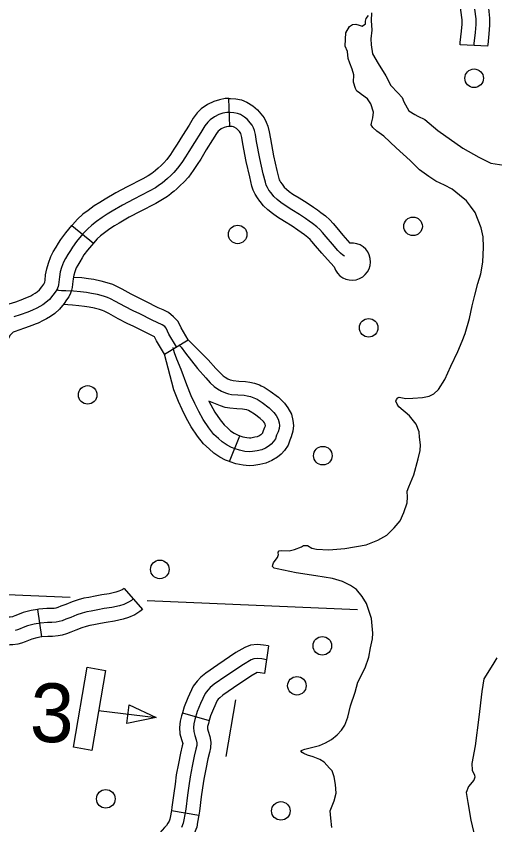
# Model space of a CAD drawing. Extents: x 653372 to 905732, y 627442 to 787275.
# Drawn here: x 712000 to 714580, y 745431 to 749788 of the extents above; entities that cross this region are included whole.
import ezdxf

# ---------------------------------------------------------------- set-up
doc = ezdxf.new("R2010")
doc.units = 0
for name, color, linetype in [('31', 7, 'Continuous'), ('32', 7, 'Continuous'), ('5', 7, 'Continuous'), ('56', 7, 'Continuous'), ('9', 7, 'Continuous')]:
    doc.layers.add(name, color=color, linetype=linetype)

msp = doc.modelspace()

# ---------------------------------------------------------------- linework, layer by layer
at = {"layer": '31'}
for p, q in [((713152, 749194.5), (713146.5, 749344.4)), ((713313.8, 748791.6), (713313.8, 748791.6)), ((712301.2, 748660.7), (712416.8, 748565)), ((712799.8, 747967.1), (712928.1, 748044.7)), ((712799.8, 747967.1), (712799.8, 747967.1)), ((713149.3, 747388.2), (713205.5, 747527.3))]:
    msp.add_line(p, q, dxfattribs=at)
for points in [[(713146.5, 749344.4), (713127.3, 749343.7), (713095.9, 749337.5), (713065.8, 749327.7), (713031.6, 749311.8), (712997.4, 749288.5), (712975.6, 749266.6), (712955.2, 749239), (712932.2, 749201.5), (712896.8, 749145.9), (712868.3, 749098.2), (712851, 749072.1), (712831.8, 749042.7), (712812, 749016.2), (712796.3, 748998.4), (712781.2, 748984.3), (712765.9, 748969.2), (712751.8, 748957.3), (712749.5, 748955.3)], [(713146.5, 749344.4), (713156.2, 749344.8), (713184.5, 749342.2), (713214.2, 749336.8), (713243.5, 749324.6), (713275.3, 749305.4), (713300.3, 749284.1), (713319.8, 749261.1), (713336.3, 749239.8), (713347.3, 749216.7), (713356.3, 749195.3), (713363.7, 749165), (713370.2, 749127), (713387.7, 749035.9), (713405, 748955.9), (713415.6, 748913.8), (713418.2, 748905.8), (713420.9, 748900), (713425.1, 748893.1), (713433.2, 748882.3)], [(713374.2, 748836), (713362.8, 748851.1), (713354.7, 748864.6), (713348.3, 748878.2), (713343.5, 748893.2), (713331.9, 748938.8), (713314.2, 749020.9), (713296.4, 749113.6), (713290.2, 749149.7), (713284.8, 749171.7), (713278.8, 749186), (713272, 749200.3), (713261.5, 749214), (713247.1, 749230.9), (713231.3, 749244.3), (713209.5, 749257.5), (713192.8, 749264.5), (713174.3, 749267.9), (713154.2, 749269.7), (713136, 749269), (713114.9, 749264.8), (713093.3, 749257.8), (713068.7, 749246.4), (713045.5, 749230.5), (713032.6, 749217.6), (713017.5, 749197.1), (712995.8, 749161.8), (712960.7, 749106.6), (712931.8, 749058.2), (712913.7, 749031), (712893.4, 748999.7), (712870.2, 748968.9), (712850.2, 748946.1), (712833.1, 748930.2), (712816.5, 748913.7), (712800.8, 748900.5), (712787.5, 748888.8), (712773.5, 748878.7), (712750.8, 748864), (712718, 748845.6), (712634.2, 748802.5), (712573.9, 748770), (712517.7, 748738), (712491, 748721.5), (712463.4, 748703.7), (712432.5, 748681.2), (712407.7, 748662.6), (712384.1, 748641.1), (712360.2, 748614.4), (712326.3, 748573.4), (712303.2, 748543.2), (712293, 748525.7), (712279, 748504.4), (712266.3, 748482.5), (712256, 748461.8), (712245, 748433.9), (712238.3, 748410.3), (712233.4, 748383.8), (712230.5, 748354.4), (712228, 748341), (712226.2, 748332.2), (712223.1, 748323), (712218.8, 748313.8), (712210.4, 748301.6), (712198.6, 748284.5), (712179.6, 748261.3), (712161.1, 748244.9), (712144.6, 748232.9), (712127.7, 748222.9), (712112.1, 748214.5), (712087.8, 748203.2), (712062.9, 748192.7), (712021.7, 748178.2), (711988.3, 748167.5)], [(713152, 749194.5), (713144.8, 749194.3), (713133.9, 749192.1), (713120.8, 749187.8), (713105.9, 749181), (713093.6, 749172.6), (713089.6, 749168.6), (713079.7, 749155.1), (713059.4, 749122), (713024.5, 749067.2), (712995.2, 749018.1), (712976.3, 748989.8), (712954.9, 748956.7), (712928.5, 748921.5), (712904, 748893.7), (712885.1, 748876.1), (712867.1, 748858.3), (712849.8, 748843.7), (712848.8, 748842.8)], [(713313.8, 748791.6), (713300.5, 748809.1), (713288.5, 748829.2), (713278.4, 748850.5), (713271.3, 748872.6), (713258.9, 748921.7), (713240.7, 749005.9), (713222.6, 749100.2), (713216.8, 749134.4), (713213.4, 749148), (713210.4, 749155.3), (713207.7, 749160.9), (713203.2, 749166.8), (713193.8, 749177.8), (713187.4, 749183.3), (713175.6, 749190.4), (713171.4, 749192.1), (713164.2, 749193.5), (713152.2, 749194.5), (713152, 749194.5)], [(712749.5, 748955.3), (712740.7, 748947.5), (712731.2, 748940.6), (712712.1, 748928.3), (712682.5, 748911.7), (712599.3, 748868.9), (712537.5, 748835.6), (712479.4, 748802.5), (712451, 748784.9), (712421.1, 748765.6), (712387.9, 748741.5), (712359.8, 748720.4), (712330.7, 748693.9), (712303.3, 748663.2), (712301.2, 748660.7)], [(713433.2, 748882.3), (713433.1, 748882.5), (713445.4, 748867.5), (713457.7, 748855.3), (713471.7, 748843.8), (713491.9, 748829.7), (713525, 748808.9), (713568.3, 748782.7), (713603.6, 748758.7), (713623.7, 748744.2), (713642.4, 748730.7), (713668.1, 748711.6), (713690.9, 748691.2), (713708.8, 748670.6), (713727.8, 748647.6), (713761.7, 748608.9), (713799, 748564.9)], [(712848.8, 748842.8), (712834.3, 748830), (712815.8, 748816.7), (712789.6, 748799.8), (712753.5, 748779.5), (712669.2, 748736.1), (712610.3, 748704.4), (712556, 748673.5), (712531, 748658), (712505.8, 748641.8), (712477.1, 748620.9), (712455.6, 748604.7), (712437.4, 748588.3), (712417.2, 748565.5), (712416.8, 748565)], [(713769.6, 748494.1), (713760.5, 748500.5), (713748.3, 748510.5), (713733.4, 748526.3), (713705, 748559.9), (713670.6, 748599), (713651.5, 748622.2), (713637.5, 748638.4), (713620.6, 748653.4), (713598.1, 748670.2), (713579.9, 748683.3), (713560.6, 748697.2), (713527.7, 748719.6), (713485.7, 748745.1), (713450.5, 748767.1), (713426.3, 748784), (713407.4, 748799.5), (713389.8, 748817), (713374.2, 748836)], [(713714.4, 748437.1), (713677.5, 748476.3), (713648.2, 748510.9), (713613.5, 748550.4), (713594.3, 748573.8), (713584, 748585.5), (713573.1, 748595.3), (713553.7, 748609.8), (713536.1, 748622.4), (713517.5, 748635.8), (713487.1, 748656.5), (713446.4, 748681.2), (713409, 748704.6), (713381, 748724.2), (713357.1, 748743.8), (713334.2, 748766.5), (713315.3, 748789.6), (713313.8, 748791.6)], [(712043.6, 748266), (712057.5, 748271.8), (712078.6, 748281.6), (712090.8, 748288.2), (712103.3, 748295.6), (712114, 748303.4), (712125.4, 748313.5), (712138.6, 748329.7), (712148.7, 748344.2), (712153.3, 748350.9), (712153.7, 748352.1), (712154.5, 748355.7), (712156.2, 748365), (712159.1, 748394.2), (712165.2, 748427.4), (712173.9, 748458), (712187.3, 748492.3), (712200.3, 748518.2), (712215.2, 748543.8), (712229.2, 748565.2), (712240.8, 748585.1), (712267.6, 748620.1), (712301.2, 748660.7)], [(712416.8, 748565), (712385, 748526.7), (712365.6, 748501.3), (712356.8, 748486.3), (712342.9, 748464.9), (712332.3, 748446.8), (712324.6, 748431.4), (712316.2, 748409.9), (712311.4, 748393.2), (712307.8, 748373.4), (712304.9, 748343.8), (712301.6, 748326.3), (712298.6, 748312.3), (712292.9, 748295.3), (712284.3, 748276.6), (712272.1, 748258.9), (712258.5, 748239.4), (712233.9, 748209.2), (712208.1, 748186.4), (712185.9, 748170.2), (712164.7, 748157.6), (712145.7, 748147.4), (712118.2, 748134.6), (712102.1, 748127.8)], [(712459.4, 748360.1), (712456.3, 748360.9), (712419.3, 748368.4), (712390.1, 748372.8), (712353.8, 748377.4), (712307.8, 748380.8)], [(712928.1, 748044.7), (712889.3, 748108.9), (712874.3, 748142.7), (712847.8, 748168.1), (712821.6, 748191.3), (712791.9, 748204.9), (712766.1, 748217.4), (712700.1, 748251.5), (712664, 748268.2), (712620.7, 748289.6), (712571.2, 748317.6), (712543.2, 748331.7), (712521.4, 748342.8), (712490.8, 748351.9), (712459.4, 748360.1)], [(712864, 748005.9), (712822.7, 748074.1), (712808.3, 748106.4), (712801.7, 748116.4), (712787.5, 748124.4), (712759.9, 748137), (712732.5, 748150.4), (712667.1, 748184.1), (712631.7, 748200.5), (712585.5, 748223.3), (712535.9, 748251.4), (712509.3, 748264.7), (712493.4, 748272.9), (712470.6, 748279.6), (712439.4, 748287.8), (712406.3, 748294.5), (712379.7, 748298.5), (712346.4, 748302.7), (712308.9, 748305.5), (712268.6, 748307.9), (712244.8, 748308.6), (712230.8, 748310.3), (712218.8, 748313.8)], [(711746.5, 748016.6), (711760.4, 748028.5), (711782.4, 748051.2), (711788.8, 748061.7), (711811.4, 748100.3), (711831.5, 748133.3), (711848.3, 748158.8), (711865.2, 748178.8), (711881.3, 748194.5), (711897.4, 748207.6), (711916.8, 748219.5), (711939.4, 748228.3), (711962.5, 748237.9), (711997.8, 748249.3), (712035.8, 748262.7), (712043.6, 748266)], [(712422.4, 748214.7), (712393.2, 748220.6), (712369.4, 748224.2), (712338.9, 748228.1), (712303.9, 748230.6), (712253.9, 748233.7)], [(712799.8, 747967.1), (712756.1, 748039.3), (712746.6, 748060.6), (712727.9, 748069.2), (712698.9, 748083.3), (712634.1, 748116.7), (712599.3, 748132.9), (712550.4, 748157), (712500.6, 748185.2), (712475.4, 748197.8), (712465.4, 748203), (712450.4, 748207.4), (712421.3, 748215)], [(712102.1, 748127.8), (712090, 748122.7), (712045.6, 748107.1), (712014.2, 748097), (711995.6, 748089.3), (711984.1, 748084.8), (711981.4, 748082.6), (711975, 748076.3), (711968.6, 748068.7), (711958.3, 748053), (711940.2, 748023.4), (711917.7, 747985), (711902, 747959), (711863.2, 747919), (711842.3, 747901.2)], [(712928.1, 748044.7), (713034.9, 747936.7), (713077.2, 747889.5), (713099.9, 747865.7), (713116, 747850.2), (713126.1, 747842.6), (713140.4, 747834.5), (713154.4, 747828.7), (713162.7, 747825.9), (713170.2, 747824.7), (713200.4, 747822.1), (713236.4, 747820.1), (713259.2, 747816.4), (713284, 747810.9), (713311.6, 747801.2), (713321.2, 747796.3)], [(712877.2, 748018), (712889.1, 748004.9), (712913.5, 747972.1), (712977.1, 747888.8), (713022.1, 747838.5), (713046.7, 747812.8), (713067.3, 747793), (713084.8, 747779.8), (713107.4, 747766.9), (713128.1, 747758.4), (713144.6, 747752.9), (713160.9, 747750.2), (713195, 747747.2), (713228.3, 747745.4), (713245, 747742.7), (713263.4, 747738.6), (713281.9, 747732.1), (713298.9, 747723.5), (713326.7, 747705.7), (713364.5, 747677.7), (713389.4, 747653), (713401.9, 747636.8), (713412.9, 747616.2), (713417.3, 747597.7), (713418.8, 747581.8), (713417.3, 747566.8), (713411.9, 747547.8), (713404.1, 747530.1), (713398.2, 747510.7), (713387.4, 747495.6), (713375.5, 747482.6), (713364.1, 747472.8), (713343.8, 747460.2), (713323.6, 747451.4), (713300, 747446.7), (713273.2, 747442.1), (713256.7, 747441.1), (713233.6, 747443.2), (713203.4, 747448.8), (713180.6, 747456.5), (713160.9, 747464.5), (713136.7, 747477.3), (713110.9, 747494), (713090.3, 747511.8), (713066.4, 747534.7), (713038.9, 747569.3), (713007.9, 747615), (712984, 747658.4), (712963.2, 747701.2), (712944.3, 747741.9), (712920.4, 747802), (712889, 747884.5), (712866.5, 747940.3), (712853.6, 747974.6), (712849.4, 747986.6), (712846.4, 748002.6)], [(713149.3, 747388.2), (713129.2, 747396.4), (713098.7, 747412.5), (713065.6, 747434), (713039.8, 747456.3), (713010.8, 747484), (712978.4, 747524.9), (712943.9, 747575.8), (712917.4, 747623.9), (712895.4, 747669), (712875.4, 747712.3), (712850.5, 747774.8), (712799.8, 747967.1)], [(713321.2, 747796.3), (713336.2, 747788.6), (713369.3, 747767.5), (713413.5, 747734.7), (713445.7, 747702.8), (713465.2, 747677.7), (713483.6, 747643), (713491.5, 747610), (713494.2, 747581.6), (713491.3, 747552.8), (713482.7, 747522.2), (713474.5, 747503.8), (713466.4, 747477.2), (713445.9, 747448.4), (713427.8, 747428.6), (713408.5, 747412.1), (713378.7, 747393.7), (713346.2, 747379.3), (713313.6, 747373), (713281.8, 747367.4), (713255.5, 747366), (713223.4, 747368.8), (713184.5, 747376.1), (713154.6, 747386.1), (713149.3, 747388.3)], [(713253, 747662.7), (713252.3, 747663), (713242.8, 747666.4), (713230.9, 747669), (713220.2, 747670.8), (713189.7, 747672.4), (713151.7, 747675.8), (713126.5, 747679.8), (713101.9, 747688.1), (713039, 747713.9)], [(713039, 747713.9), (713071.9, 747654.2), (713099.4, 747613.7), (713121.9, 747585.4), (713140.8, 747567.4), (713156.1, 747554.1), (713174.7, 747542), (713192.6, 747532.6), (713205.5, 747527.3)], [(713205.5, 747527.3), (713206.6, 747526.9), (713222.4, 747521.6), (713243.9, 747517.6), (713257.9, 747516.3), (713264.6, 747516.7), (713286.3, 747520.5), (713301.1, 747523.4), (713308.8, 747526.8), (713319.7, 747533.5), (713323.2, 747536.5), (713329, 747542.8), (713330, 747544.3), (713333.7, 747556.3), (713341.2, 747573.3), (713343.4, 747580.8), (713343.5, 747582), (713343.1, 747585.4), (713342.2, 747589.5), (713338.7, 747596), (713333.1, 747603.2), (713315.6, 747620.6), (713284.1, 747643.9), (713261.6, 747658.3), (713253, 747662.7)]]:
    msp.add_lwpolyline(points, dxfattribs=at)
msp.add_arc((713810.3, 748465.5), 100, 196.5446, 96.4681, dxfattribs=at)
at = {"layer": '32'}
for p, q in [((714543.2, 749626.7), (714393.4, 749633.7)), ((712582.2, 746704.2), (712681.5, 746591.8)), ((712114.7, 746591.2), (712137.3, 746442.9)), ((713360.7, 746394.7), (713338.9, 746246.3)), ((712896.3, 746034.2), (713040.6, 745993)), ((712837, 745507.7), (712985, 745483.1))]:
    msp.add_line(p, q, dxfattribs=at)
for points in [[(714393.4, 749633.7), (714394, 749646.2), (714400.9, 749707.2), (714403.9, 749745.9), (714403.8, 749768.6), (714397.5, 749821), (714396.3, 749860.7), (714399, 749909.5), (714409, 749947.5), (714422.3, 749979.9), (714449.7, 750029.4), (714481.1, 750071.2), (714509.2, 750102.2), (714531.6, 750125.1), (714546.8, 750143.7), (714558.6, 750158)], [(714543.2, 749626.7), (714543.6, 749634.2), (714550.3, 749693), (714553.9, 749740.4), (714553.8, 749777.9), (714547.2, 749832.2), (714546.4, 749858.7), (714547.9, 749886), (714551.6, 749899.8), (714557.8, 749914.9), (714575.9, 749947.7), (714596.8, 749975.5), (714618.4, 749999.3), (714643.6, 750025.1), (714662.7, 750048.5), (714674.2, 750062.4)], [(714468.3, 749630.2), (714468.8, 749640.2), (714475.6, 749700.1), (714478.9, 749743.2), (714478.8, 749773.2), (714472.4, 749826.6)], [(712582.2, 746704.2), (712577.8, 746700.3), (712571.2, 746696.3), (712554.1, 746689), (712537.2, 746683.7), (712501.9, 746675.5), (712461.3, 746669.6), (712426.1, 746662.9), (712391.7, 746655.7), (712365.9, 746651.6), (712335.2, 746643.5), (712301.9, 746632.6), (712267.3, 746618.4), (712240.7, 746608.5), (712224.5, 746601.9), (712213.6, 746599), (712204.7, 746597.1), (712189.5, 746596), (712164.9, 746595.6), (712122.5, 746592.4), (712114.6, 746591.2)], [(712631.8, 746648), (712622.5, 746639.8), (712605.9, 746629.6), (712580.1, 746618.5), (712556.7, 746611.3), (712515.8, 746601.8), (712473.8, 746595.7), (712440.8, 746589.3), (712405.3, 746581.9), (712381.4, 746578.1), (712356.4, 746571.5), (712327.8, 746562.2), (712294.7, 746548.5), (712267.8, 746538.6), (712248.4, 746530.7), (712231.3, 746526.1), (712215.4, 746522.7), (712192.7, 746521.1), (712168.4, 746520.7), (712131, 746517.8), (712097, 746512.6), (712061.4, 746503), (712037.4, 746493.5), (712021.3, 746486.1), (712007.1, 746481.4), (711994.5, 746477.9)], [(712114.7, 746591.2), (712081.4, 746586.1), (712037.7, 746574.3), (712007.8, 746562.5), (711993.8, 746556), (711985.1, 746553.2), (711979.8, 746551.6), (711967.9, 746550.3), (711952.3, 746549), (711920.3, 746545), (711879, 746534.2), (711832.9, 746517.4), (711779.8, 746493.1), (711732.1, 746467.9), (711695, 746451), (711681.4, 746446.5), (711656.9, 746441.9), (711564.8, 746435.5)], [(712681.5, 746591.8), (712667.3, 746579.3), (712640.5, 746562.8), (712606.1, 746548), (712576.3, 746538.8), (712529.6, 746528), (712486.3, 746521.7), (712455.5, 746515.8), (712418.8, 746508.2), (712396.9, 746504.7), (712377.6, 746499.6), (712353.8, 746491.8), (712322, 746478.7), (712294.9, 746468.7), (712272.3, 746459.5), (712249, 746453.2), (712226, 746448.2), (712195.9, 746446.1), (712171.9, 746445.7), (712139.5, 746443.3), (712137.3, 746442.9)], [(712137.3, 746442.9), (712112.5, 746439.1), (712085, 746431.7), (712066.9, 746424.5), (712048.8, 746416.2), (712029, 746409.7), (712009.3, 746404.1), (711982.6, 746401), (711967.6, 746399.7), (711948.6, 746397.4), (711923.8, 746390.9), (711889.9, 746378.5), (711846, 746358.4), (711798.3, 746333.3), (711749.6, 746311), (711718.7, 746300.9), (711676.1, 746292.9), (711638.8, 746290.3), (711580.6, 746293.5)], [(713360.7, 746394.7), (713333.5, 746398.7), (713301.1, 746402), (713263.6, 746399.5), (713233, 746386.6), (713184.8, 746358.5), (713087.6, 746293.1), (713022.8, 746248.5), (712995.8, 746225.9), (712975.4, 746205.1), (712954.7, 746177.3), (712925.9, 746115.3), (712905.6, 746066.8), (712896.3, 746034.2)], [(713349.8, 746320.5), (713324.2, 746324.3), (713299.7, 746326.8), (713281.2, 746325.5), (713266.6, 746319.4), (713224.7, 746295), (713129.9, 746231.1), (713068.2, 746188.7), (713046.8, 746170.8), (713032.6, 746156.3), (713019.5, 746138.7), (712994.6, 746085.1), (712976.5, 746041.9), (712963.8, 745997.5), (712957.8, 745975.5), (712955.4, 745954.7), (712957.1, 745933.7), (712963.1, 745912.6), (712971.3, 745888.4), (712974.4, 745871.6), (712973.4, 745857.9), (712968.6, 745838.3), (712959.9, 745801.3), (712949.2, 745746), (712937.3, 745688.4), (712931.1, 745640.1), (712923.7, 745591.3), (712914.2, 745514.5), (712904.7, 745457.3), (712901.2, 745438.8), (712892.1, 745416.9)], [(713338.9, 746246.3), (713314.9, 746249.8), (713299, 746251.5), (713264.5, 746231.4), (713172.1, 746169.1), (713113.6, 746128.8), (713097.7, 746115.6), (713089.7, 746107.4), (713084.2, 746100.1), (713063.2, 746054.8), (713047.4, 746017.1), (713040.6, 745993)], [(712896.3, 746034.2), (712891.6, 746017.7), (712884, 745989.9), (712880, 745955.9), (712883, 745920.3), (712891.4, 745890.3), (712898.6, 745869.5), (712898.8, 745868.3), (712895.7, 745855.8), (712886.5, 745817), (712875.7, 745760.7), (712863.3, 745700.8), (712856.8, 745650.6), (712849.4, 745601.6), (712839.9, 745525.2), (712837, 745507.7)], [(713040.6, 745993), (713036.1, 745977.2), (713031.6, 745961.2), (713030.7, 745953.5), (713031.3, 745947.1), (713034.7, 745934.9), (713044.1, 745907.4), (713049.9, 745875.7), (713047.7, 745846.2), (713041.5, 745820.8), (713033.2, 745785.6), (713022.8, 745731.4), (713011.4, 745676), (713005.4, 745629.7), (712998, 745581.1), (712988.4, 745503.7), (712985, 745483.1)], [(712837, 745507.7), (712830.9, 745470.5), (712828.9, 745460.4), (712824.7, 745450.2), (712818.5, 745439.4), (712811.3, 745427.1), (712800.5, 745415.4), (712762.2, 745373.1), (712733.7, 745343.7), (712685.3, 745308.4), (712613.3, 745261.1)], [(712985, 745483.1), (712978.5, 745444.2), (712973.4, 745417.2), (712959.6, 745383.7), (712948.1, 745364), (712932.6, 745337.4), (712911.3, 745314.3), (712871.7, 745270.4), (712803.5, 745200.4)]]:
    msp.add_lwpolyline(points, dxfattribs=at)
at = {"layer": '5'}
for points in [[(712290.9, 746655.2), (711527, 746687.9)], [(713839.3, 746588.9), (712706.3, 746637.4)]]:
    msp.add_lwpolyline(points, dxfattribs=at)
at = {"layer": '56'}
for p, q in [((712596.9, 745976.8), (712609.5, 746078)), ((712609.5, 746078), (712755.1, 746008.5)), ((712755.1, 746008.5), (712596.9, 745976.8))]:
    msp.add_line(p, q, dxfattribs=at)
msp.add_lwpolyline([(712383.2, 746279.5), (712481.8, 746262.7), (712408.2, 745831.4), (712309.7, 745848.2)], close=True, dxfattribs=at)
for points in [[(713182.5, 746103.4), (713130.6, 745799)], [(712445, 746047), (712755.1, 746008.5)]]:
    msp.add_lwpolyline(points, dxfattribs=at)
for centre in [(714468.5, 749453.7), (714139.4, 748655.6), (713194, 748612.1), (713900.2, 748109), (712385.7, 747747.4), (713653.1, 747419.8), (712774.6, 746806.9), (713650.5, 746395.3), (713513.3, 746180), (712483.4, 745570.5), (713427, 745505.6)]:
    msp.add_circle(centre, 50, dxfattribs=at)
at = {"layer": '9'}
for points in [[(714557.8, 748995.4), (714629.3, 748985.8), (714700.8, 749002.5), (714762, 749021.6), (714811.4, 749066.1), (714901.7, 749149.1), (714975.3, 749234.7), (715045.3, 749337.2), (715083.1, 749413.4), (715099.3, 749465.2), (715106, 749479.6), (715132.1, 749512.3), (715171.4, 749569.7), (715204.4, 749623), (715257.7, 749728.1), (715315, 749826.7)], [(714507.3, 748647.3), (714473.2, 748729.6), (714449.5, 748764.5), (714426.8, 748793.5), (714388.9, 748824.1), (714349.8, 748855.9), (714309.2, 748878.4), (714262.7, 748898.6), (714224.6, 748924.5), (714173.8, 748960.2), (714124.6, 749010), (714048.9, 749078.3), (713982.5, 749141.6), (713944.4, 749168.7), (713922.6, 749188.2), (713913.6, 749202.6), (713916.2, 749212), (713923, 749241.2), (713926.3, 749271.8), (713912.3, 749315.8), (713893, 749342.3), (713862, 749366.8), (713845.8, 749378.6), (713836.6, 749384.8), (713828.8, 749399.2), (713819.2, 749432.5), (713820.4, 749472.5), (713811.9, 749503.4), (713798.7, 749534.4), (713790, 749560.6), (713785.2, 749597.3), (713774.3, 749625.9), (713775.4, 749663.6), (713777.7, 749698.9), (713797.5, 749732.5), (713813.2, 749742.6), (713830.9, 749745.6), (713848.4, 749739.2), (713866, 749735.2), (713882.8, 749746.4), (713883.3, 749761.8), (713886, 749775.8), (713899.5, 749791.9)], [(713915.2, 749806.8), (713912.8, 749765.6), (713917.2, 749713.6), (713911, 749666.6), (713913.6, 749633.5), (713921.5, 749585)], [(713921.5, 749585), (713950.6, 749533.4), (713992.2, 749466.2), (714018.9, 749414.7), (714056.6, 749374.6), (714080.6, 749350.3), (714090.5, 749326.5), (714117.4, 749278.5), (714148.6, 749258.7), (714166, 749249.9), (714203.1, 749231.2), (714272, 749171.3), (714408.3, 749077.7), (714494, 749027.9), (714557.8, 748995.4)], [(713549.8, 746935.9), (713569.8, 746936.5), (713594.1, 746921.6), (713618.7, 746916.2), (713685.8, 746913), (713770.8, 746919.9), (713886.9, 746938.8), (713948.9, 746964), (713998, 746992), (714036.9, 747030.9), (714069.9, 747068.8), (714090.1, 747113.6), (714106.9, 747165), (714109.1, 747196.8), (714107.7, 747228.6), (714116.6, 747251.9), (714143.3, 747317.1), (714167.1, 747402.5), (714177.9, 747448.1), (714179.9, 747477.5), (714174.1, 747519), (714171.5, 747548.5), (714156.2, 747589), (714119.8, 747633.7), (714063.6, 747683.8), (714054.6, 747697), (714046.8, 747713.7), (714050.6, 747721.9), (714058, 747732.3), (714065.1, 747734.4), (714100.3, 747728.6), (714138, 747729.8), (714190, 747733), (714226.7, 747740.2), (714250.6, 747752.4), (714277.3, 747776.4), (714310.7, 747829.6), (714343.5, 747901.7), (714381.3, 747981.9), (714404.1, 748036.6), (714419.5, 748078.5), (714443.1, 748158.8), (714458.1, 748226.7), (714472.8, 748284), (714488.9, 748348.4), (714504.6, 748399.7), (714515.9, 748463), (714518.3, 748543.2), (714517.6, 748598.7), (714507.3, 748647.3)], [(713715, 745688.7), (713704.2, 745720.9), (713688.2, 745736.7), (713659.6, 745768.2), (713636.5, 745781.8), (713601.6, 745797), (713570, 745805.1), (713550.3, 745815.1), (713541, 745820.1), (713534.2, 745828.5), (713536.7, 745832), (713556.9, 745838.4), (713635.2, 745857.3), (713667.5, 745871.7), (713699.9, 745890.7), (713731.2, 745915.7), (713753.2, 745941), (713771.7, 745968.1), (713787.1, 746010.1), (713803.1, 746072.1), (713826.5, 746145.7), (713841.1, 746199.4), (713881.1, 746276), (713901.7, 746334.4), (713910.3, 746384.8), (713921.2, 746432.8), (713923.3, 746463.4), (713915, 746541.9), (713889.2, 746624), (713865.5, 746660.1), (713834.9, 746698.7), (713802.5, 746720.9), (713758.4, 746741.1), (713705.9, 746758), (713615.6, 746772.5), (713510, 746788.6), (713407, 746810.6), (713391.7, 746813.4), (713382.6, 746821.9), (713384, 746831.3), (713387.9, 746843), (713396.5, 746854.5), (713408.8, 746871.8), (713414, 746888.1), (713411.9, 746895.3), (713412, 746900), (713418.1, 746906.9), (713428.8, 746908.9), (713472.3, 746907.6), (713499.6, 746913.9), (713537.8, 746929.2), (713549.8, 746935.9)], [(714591.1, 746329.9), (714569.1, 746295)], [(714569.1, 746295), (714520.8, 746217.2), (714510.4, 746148.6), (714493.7, 746011.1), (714474.5, 745856.9), (714457, 745761.3), (714458, 745725.7), (714469.7, 745698.1), (714471.5, 745687.6), (714466.8, 745671.1), (714438.6, 745636.4), (714425.1, 745605.4), (714433.9, 745550.8), (714449.9, 745456.2), (714479.7, 745334), (714520.6, 745165.5), (714561.7, 745072.3), (714599.9, 745021)], [(713700.9, 745415.7), (713695.4, 745466.5), (713693, 745506.7), (713713.5, 745559.1), (713724.2, 745601.2), (713722, 745647.3), (713715, 745688.7)]]:
    msp.add_lwpolyline(points, dxfattribs=at)

# ---------------------------------------------------------------- texts
at = {"layer": '56'}
msp.add_text('3', height=316.8, rotation=358.28, dxfattribs=at).set_placement((712071.6, 745879.6))

doc.saveas('drawing.dxf')
